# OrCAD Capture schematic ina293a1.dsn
size A; title: INA293 40-V High-Voltage, High Bandwidth, Unidirectional, 110-V Common-Mode Current-Sense Amplifier; rev: A; note: SBOS870
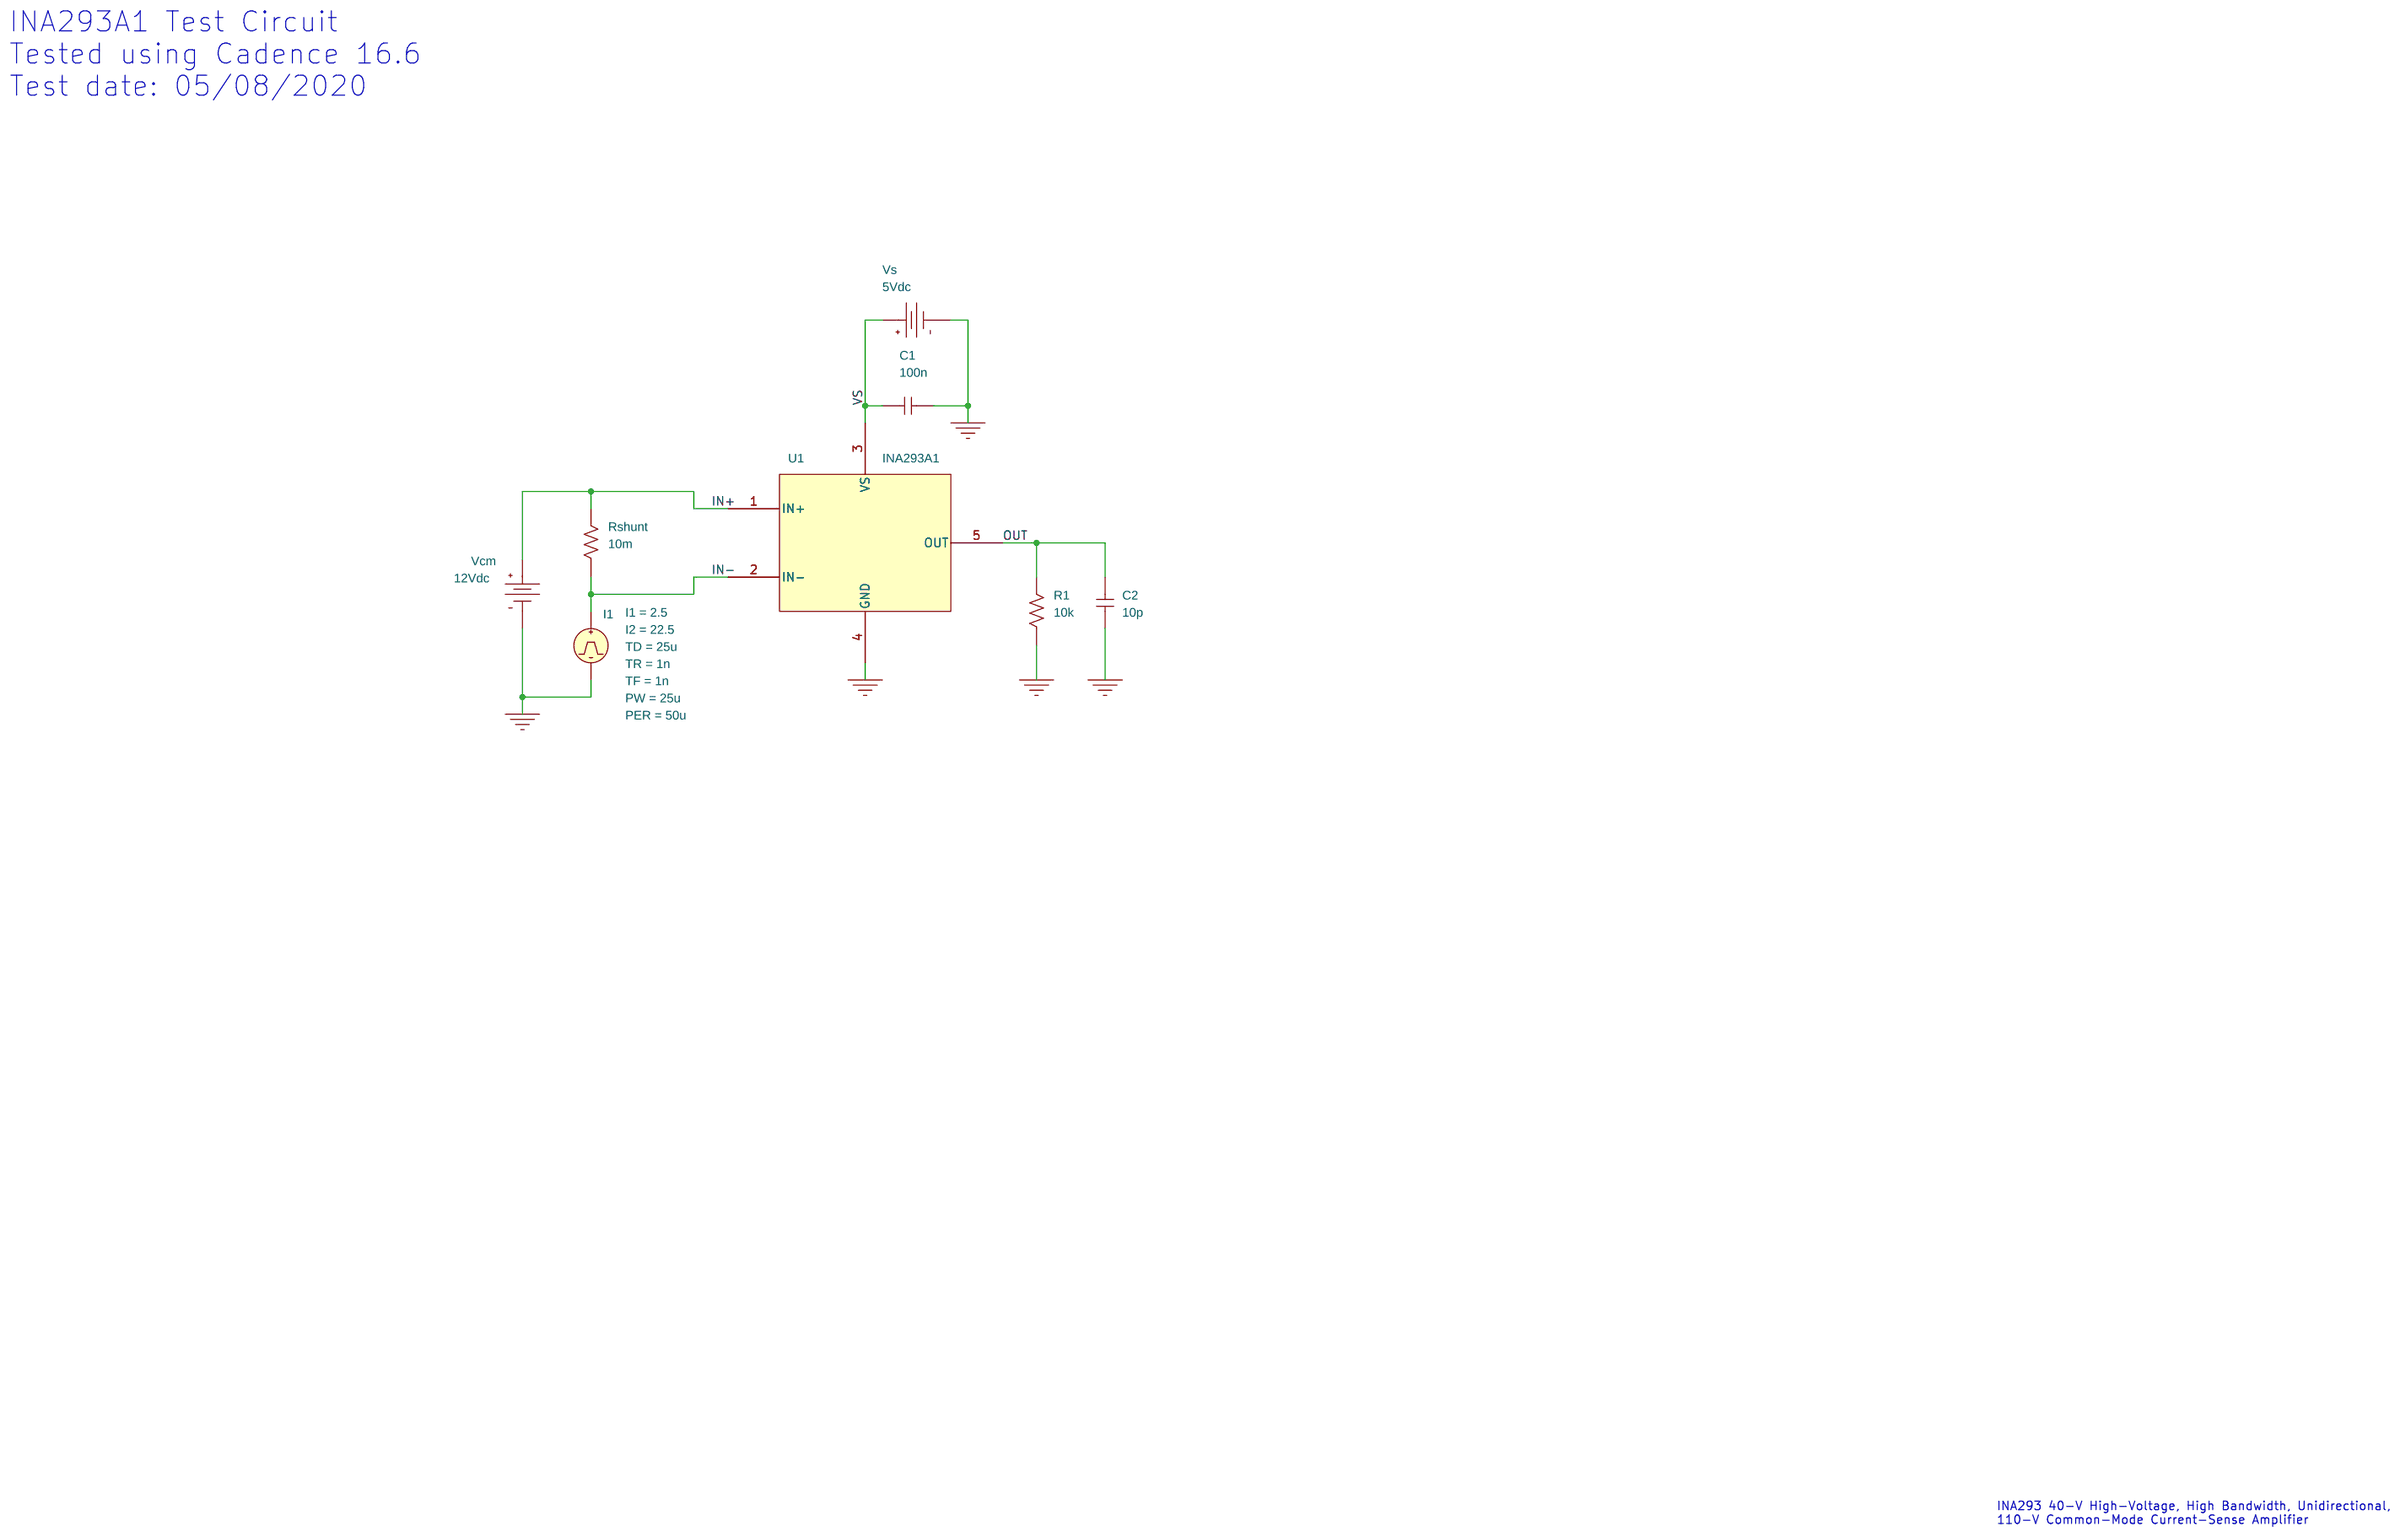
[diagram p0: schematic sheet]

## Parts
C1  100n  [RAD/CK05]
C2  10p  [RAD/CK05]
I1  IPULSE
R1  10k  [AX/RC05]
Rshunt  10m  [AX/RC05]
U1  INA293A1
Vcm  VDC
Vs  VDC

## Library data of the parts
C1 C2 = C
I1 = IPULSE: I1: 2.5; I2: 22.5; PER: 50u; PW: 25u; TD: 25u; TF: 1n; TR: 1n
R1 Rshunt = R
U1 = INA293A1_0
Vcm = VDC: DC: 12Vdc
Vs = VDC: DC: 5Vdc

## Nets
0: C1.1 C2.1 I1.2(-) R1.1 U1.4(GND) Vcm.1(-) Vs.1(-)
IN+: Rshunt.2 U1.1(IN+) Vcm.0(+)
IN-: I1.1(+) Rshunt.1 U1.2(IN-)
OUT: C2.2 R1.2 U1.5(OUT)
VS: C1.2 U1.3(VS) Vs.0(+)

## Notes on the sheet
- INA293A1 Test Circuit
  Tested using Cadence 16.6
  Test date: 05/08/2020
- INA293 40-V High-Voltage, High Bandwidth, Unidirectional,
  110-V Common-Mode Current-Sense Amplifier
